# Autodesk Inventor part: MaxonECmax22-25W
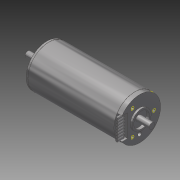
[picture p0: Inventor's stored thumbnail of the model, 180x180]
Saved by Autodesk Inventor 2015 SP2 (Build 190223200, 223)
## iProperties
Created: 2015-08
Part Number: MaxonECmax22-25W
Material: Eisen, schmiedbar
Document SubType Name: Modeling
Designer: rYan
Mass: 131.802 g
Surface Area: 47.345 cm^2
Volume: 18.4338 cm^3
Density: 7.15 g/cm^3
Appearance: Halbpoliert
Author: MMAGBRD
Title: 916774_ASM
Sending System: PRO/ENGINEER BY PARAMETRIC TECHNOLOGY CORPORATION, 2009230
Preprocessor: PRO/ENGINEER BY PARAMETRIC TECHNOLOGY CORPORATION, 2009230
Author: rYan
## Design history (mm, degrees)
node "EC-max22-2838561"
workplane "Arbeitsebene2"
sketch "Skizze2"
  geometry: L1 (33.792, 12.879)-(52.099, 12.879); L2 (52.099, 12.879)-(52.099, -14.305); L3 (52.099, -14.305)-(33.792, -14.305); L4 (33.792, -14.305)-(33.792, 12.879); 1 further point
  constraints: 8 end point, 2 parallel, 1 horizontal, 1 perpendicular
extrude "Extrusion1" cut sketch "Skizze2" stored distance "d4" = 10; taper "d5" = 0 deg
node "Volumenkörper1"
node "Basis1"
feature "Zusammengesetzt1"
node "Fläche1"
